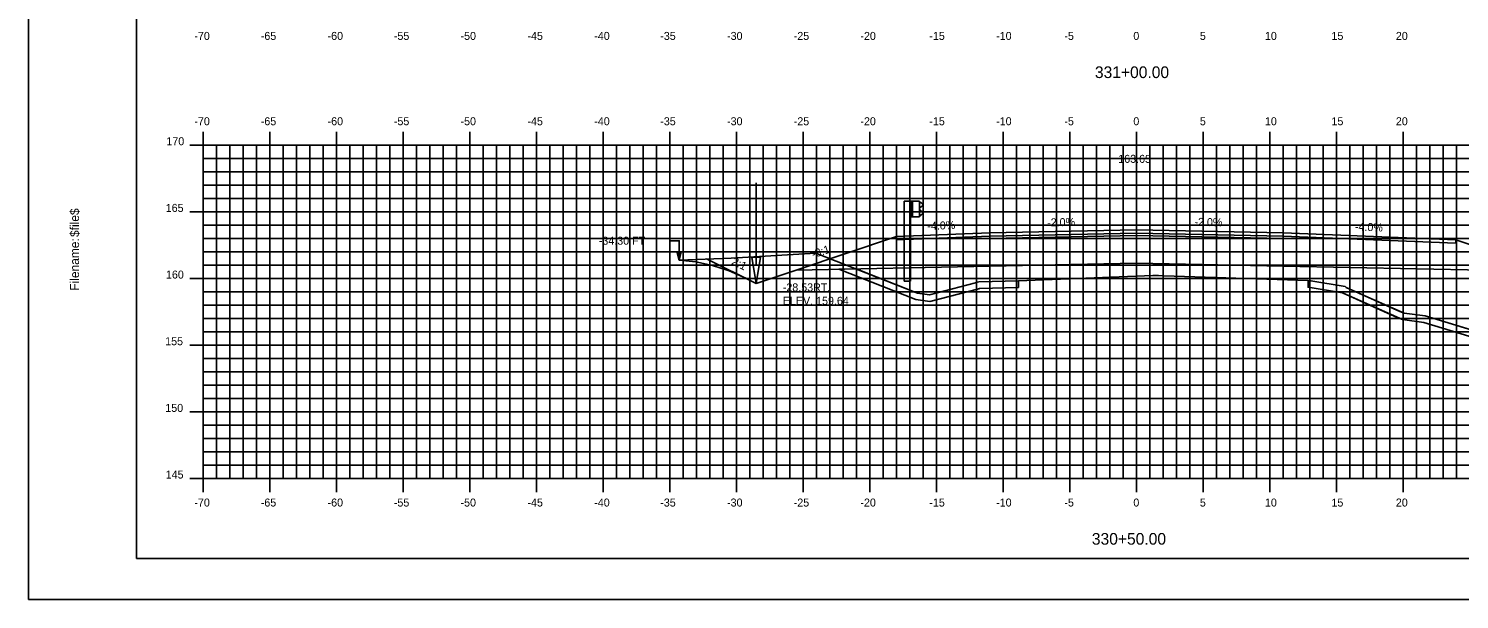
# Model space of a CAD drawing. Extents: x 1141424 to 1141594, y 608981 to 609091.
# Drawn here: x 1141424.2 to 1141531.5, y 608981.3 to 609024.1 of the extents above; entities that cross this region are included whole.
import ezdxf

# ---------------------------------------------------------------- set-up
doc = ezdxf.new("R2010")
doc.units = 0
for name, color, linetype in [('ANNOTATION', 7, 'Continuous'), ('BORDER', 7, 'Continuous'), ('D_Drainage_Ditch_Line', 7, 'Continuous'), ('D_Guardrail_Beam_Lt', 7, 'Continuous'), ('D_Roadway_Centerline', 7, 'Continuous'), ('D_Roadway_Centerline_Text', 7, 'Continuous'), ('D_Roadway_Edge_Shoulder', 7, 'Continuous'), ('D_Roadway_Edge_TW', 7, 'Continuous'), ('D_Roadway_Pavement', 7, 'Continuous'), ('D_Roadway_SlopeLines', 7, 'Continuous'), ('D_Roadway_SubGrade', 7, 'Continuous'), ('D_Text_Standard', 7, 'Continuous'), ('H_V ANNOTATION', 7, 'Continuous'), ('MAJOR', 7, 'Continuous'), ('MINOR', 7, 'Continuous'), ('PLOT BOUNDARY', 7, 'Continuous'), ('S_Roadway_Centerline', 7, 'Continuous'), ('SHADING', 7, 'Continuous')]:
    doc.layers.add(name, color=color, linetype=linetype)

msp = doc.modelspace()

# ---------------------------------------------------------------- linework, layer by layer
msp.add_lwpolyline([(1141475.03, 609006.83), (1141478.74, 609004.98), (1141481.74, 609005.98), (1141489.27, 609008.49), (1141489.27, 609008.49), (1141496.27, 609008.77), (1141507.27, 609008.99), (1141518.27, 609008.77), (1141531.21, 609008.25), (1141538.37, 609005.87), (1141541.37, 609004.87), (1141564.04, 608997.31)])
at = {"layer": 'BORDER'}
msp.add_lwpolyline([(1141432.27, 608984.34), (1141592.27, 608984.34), (1141592.27, 609089.34), (1141432.27, 609089.34)], close=True, dxfattribs=at)
at = {"layer": 'D_Drainage_Ditch_Line'}
msp.add_line((1141478.74, 609006.29), (1141478.74, 609012.53), dxfattribs=at)
msp.add_line((1141478.74, 609006.29), (1141478.74, 609012.53), dxfattribs=at)
msp.add_lwpolyline([(1141478.41, 609006.95), (1141479.07, 609006.95), (1141478.74, 609004.98)], close=True, dxfattribs=at)
msp.add_lwpolyline([(1141478.41, 609006.95), (1141479.07, 609006.95), (1141478.74, 609004.98)], close=True, dxfattribs=at)
at = {"layer": 'D_Guardrail_Beam_Lt'}
for p, q in [((1141489.84, 609011.15), (1141489.84, 609005.15)), ((1141490.31, 609011.15), (1141489.84, 609011.15)), ((1141491, 609011.15), (1141490.31, 609011.15)), ((1141490.31, 609011.15), (1141490.31, 609009.98)), ((1141490.37, 609011.15), (1141490.37, 609009.98)), ((1141490.48, 609011.15), (1141490.48, 609009.98)), ((1141491, 609009.98), (1141491, 609011.15)), ((1141491, 609011.07), (1141491.07, 609011.05)), ((1141491, 609010.6), (1141491, 609010.53)), ((1141491.23, 609010.8), (1141491.04, 609010.67)), ((1141491.04, 609010.47), (1141491.23, 609010.33)), ((1141491.09, 609011.05), (1141491.23, 609010.95)), ((1141490.31, 609009.98), (1141491, 609009.98)), ((1141490.33, 609005.15), (1141490.33, 609009.98)), ((1141491.07, 609010.08), (1141491, 609010.07)), ((1141491.23, 609010.19), (1141491.09, 609010.09)), ((1141490.33, 609005.15), (1141489.84, 609005.15))]:
    msp.add_line(p, q, dxfattribs=at)
for centre, major_axis, start_param, end_param in [((1141491.08, 609010.6), (-0.0789, 0), 5.323254, 6.283185), ((1141491.08, 609010.53), (-0.0789, 0), 6.283185, 7.243116), ((1141491.07, 609011.01), (0.0417, 0), 0.959931, 1.376053), ((1141491.18, 609010.88), (0.0877, 0), 5.323254, 7.243116), ((1141491.18, 609010.26), (0.0877, 0), 5.323254, 7.243116), ((1141491.07, 609010.12), (0.0417, 0), 4.907132, 5.323254)]:
    msp.add_ellipse(centre, major_axis=major_axis, ratio=0.995501, start_param=start_param, end_param=end_param, dxfattribs=at)
at = {"layer": 'D_Roadway_Edge_Shoulder'}
for points in [[(1141496.27, 609008.77), (1141489.27, 609008.49), (1141489.27, 609008.24), (1141496.27, 609008.52)], [(1141518.27, 609008.77), (1141531.21, 609008.25), (1141531.21, 609008), (1141518.27, 609008.52)]]:
    msp.add_lwpolyline(points, close=True, dxfattribs=at)
at = {"layer": 'D_Roadway_Edge_TW'}
msp.add_lwpolyline([(1141496.27, 609008.52), (1141496.27, 609008.77), (1141507.27, 609008.99), (1141518.27, 609008.77), (1141518.27, 609008.52), (1141507.27, 609008.74)], close=True, dxfattribs=at)
at = {"layer": 'D_Roadway_Pavement'}
msp.add_lwpolyline([(1141496.27, 609008.35), (1141496.27, 609008.52), (1141507.27, 609008.74), (1141518.27, 609008.52), (1141518.27, 609008.35), (1141507.27, 609008.57)], close=True, dxfattribs=at)
at = {"layer": 'D_Roadway_SlopeLines'}
for p, q in [((1141498.41, 609005.18), (1141498.41, 609004.68)), ((1141520.14, 609005.19), (1141520.14, 609004.69))]:
    msp.add_line(p, q, dxfattribs=at)
for points in [[(1141478.74, 609004.98), (1141477.97, 609005.36), (1141476.72, 609005.91), (1141475.47, 609006.33), (1141474.22, 609006.6), (1141472.97, 609006.72)], [(1141484.94, 609006.04), (1141490.71, 609003.76), (1141491.78, 609003.63), (1141495.35, 609004.54), (1141495.45, 609004.58), (1141495.5, 609004.59), (1141498.41, 609004.68)], [(1141481.74, 609005.98), (1141478.74, 609004.98)], [(1141520.14, 609004.69), (1141520.3, 609004.68), (1141522.72, 609004.26), (1141522.76, 609004.24), (1141526.82, 609002.42), (1141527.22, 609002.26), (1141528.81, 609002.05), (1141538.37, 608999.14)]]:
    msp.add_lwpolyline(points, dxfattribs=at)
at = {"layer": 'D_Roadway_SubGrade'}
for points in [[(1141496.27, 609008.35), (1141496.27, 609008.52), (1141489.27, 609008.24), (1141489.27, 609008.49), (1141489.27, 609008.49), (1141481.74, 609005.98), (1141496.27, 609006.27)], [(1141496.27, 609006.27), (1141496.27, 609008.35), (1141507.27, 609008.57), (1141518.27, 609008.35), (1141518.27, 609006.27), (1141507.27, 609006.49)], [(1141518.27, 609008.35), (1141518.27, 609008.52), (1141531.21, 609008), (1141531.21, 609008.25), (1141531.21, 609008.25), (1141538.37, 609005.87), (1141518.27, 609006.27)]]:
    msp.add_lwpolyline(points, close=True, dxfattribs=at)
at = {"layer": 'D_Text_Standard'}
msp.add_lwpolyline([(1141472.97, 609006.72), (1141472.97, 609008.18), (1141472.29, 609008.18)], dxfattribs=at)
msp.add_lwpolyline([(1141472.97, 609006.72), (1141472.83, 609007.3), (1141473.12, 609007.31)], close=True, dxfattribs=at)
at = {"layer": 'MAJOR'}
for p, q in [((1141437.27, 609016.34), (1141437.27, 609015.34)), ((1141442.27, 609016.34), (1141442.27, 609015.34)), ((1141447.27, 609016.34), (1141447.27, 609015.34)), ((1141452.27, 609016.34), (1141452.27, 609015.34)), ((1141457.27, 609016.34), (1141457.27, 609015.34)), ((1141462.27, 609016.34), (1141462.27, 609015.34)), ((1141467.27, 609016.34), (1141467.27, 609015.34)), ((1141472.27, 609016.34), (1141472.27, 609015.34)), ((1141477.27, 609016.34), (1141477.27, 609015.34)), ((1141482.27, 609016.34), (1141482.27, 609015.34)), ((1141487.27, 609016.34), (1141487.27, 609015.34)), ((1141492.27, 609016.34), (1141492.27, 609015.34)), ((1141497.27, 609016.34), (1141497.27, 609015.34)), ((1141502.27, 609016.34), (1141502.27, 609015.34)), ((1141507.27, 609016.34), (1141507.27, 609015.34)), ((1141512.27, 609016.34), (1141512.27, 609015.34)), ((1141517.27, 609016.34), (1141517.27, 609015.34)), ((1141522.27, 609016.34), (1141522.27, 609015.34)), ((1141527.27, 609016.34), (1141527.27, 609015.34)), ((1141436.27, 609015.34), (1141437.27, 609015.34)), ((1141437.27, 609015.34), (1141577.27, 609015.34)), ((1141437.27, 608990.34), (1141437.27, 609015.34)), ((1141437.27, 608990.34), (1141437.27, 609015.34)), ((1141437.27, 609015.34), (1141577.27, 609015.34)), ((1141442.27, 608990.34), (1141442.27, 609015.34)), ((1141447.27, 608990.34), (1141447.27, 609015.34)), ((1141452.27, 608990.34), (1141452.27, 609015.34)), ((1141457.27, 608990.34), (1141457.27, 609015.34)), ((1141462.27, 608990.34), (1141462.27, 609015.34)), ((1141467.27, 608990.34), (1141467.27, 609015.34)), ((1141472.27, 608990.34), (1141472.27, 609015.34)), ((1141477.27, 608990.34), (1141477.27, 609015.34)), ((1141482.27, 608990.34), (1141482.27, 609015.34)), ((1141487.27, 608990.34), (1141487.27, 609015.34)), ((1141492.27, 608990.34), (1141492.27, 609015.34)), ((1141497.27, 608990.34), (1141497.27, 609015.34)), ((1141502.27, 608990.34), (1141502.27, 609015.34)), ((1141507.27, 608990.34), (1141507.27, 609015.34)), ((1141512.27, 608990.34), (1141512.27, 609015.34)), ((1141517.27, 608990.34), (1141517.27, 609015.34)), ((1141522.27, 608990.34), (1141522.27, 609015.34)), ((1141527.27, 608990.34), (1141527.27, 609015.34)), ((1141436.27, 609010.34), (1141437.27, 609010.34)), ((1141437.27, 609010.34), (1141577.27, 609010.34)), ((1141436.27, 609005.34), (1141437.27, 609005.34)), ((1141437.27, 609005.34), (1141577.27, 609005.34)), ((1141436.27, 609000.34), (1141437.27, 609000.34)), ((1141437.27, 609000.34), (1141577.27, 609000.34)), ((1141436.27, 608995.34), (1141437.27, 608995.34)), ((1141437.27, 608995.34), (1141577.27, 608995.34)), ((1141436.27, 608990.34), (1141437.27, 608990.34)), ((1141437.27, 608990.34), (1141577.27, 608990.34)), ((1141437.27, 608990.34), (1141577.27, 608990.34)), ((1141437.27, 608989.33), (1141437.27, 608990.34)), ((1141442.27, 608989.33), (1141442.27, 608990.34)), ((1141447.27, 608989.33), (1141447.27, 608990.34)), ((1141452.27, 608989.33), (1141452.27, 608990.34)), ((1141457.27, 608989.33), (1141457.27, 608990.34)), ((1141462.27, 608989.33), (1141462.27, 608990.34)), ((1141467.27, 608989.33), (1141467.27, 608990.34)), ((1141472.27, 608989.33), (1141472.27, 608990.34)), ((1141477.27, 608989.33), (1141477.27, 608990.34)), ((1141482.27, 608989.33), (1141482.27, 608990.34)), ((1141487.27, 608989.33), (1141487.27, 608990.34)), ((1141492.27, 608989.33), (1141492.27, 608990.34)), ((1141497.27, 608989.33), (1141497.27, 608990.34)), ((1141502.27, 608989.33), (1141502.27, 608990.34)), ((1141507.27, 608989.33), (1141507.27, 608990.34)), ((1141512.27, 608989.33), (1141512.27, 608990.34)), ((1141517.27, 608989.33), (1141517.27, 608990.34)), ((1141522.27, 608989.33), (1141522.27, 608990.34)), ((1141527.27, 608989.33), (1141527.27, 608990.34))]:
    msp.add_line(p, q, dxfattribs=at)
at = {"layer": 'MINOR'}
for p, q in [((1141438.27, 608990.34), (1141438.27, 609015.34)), ((1141439.27, 608990.34), (1141439.27, 609015.34)), ((1141440.27, 608990.34), (1141440.27, 609015.34)), ((1141441.27, 608990.34), (1141441.27, 609015.34)), ((1141443.27, 608990.34), (1141443.27, 609015.34)), ((1141444.27, 608990.34), (1141444.27, 609015.34)), ((1141445.27, 608990.34), (1141445.27, 609015.34)), ((1141446.27, 608990.34), (1141446.27, 609015.34)), ((1141448.27, 608990.34), (1141448.27, 609015.34)), ((1141449.27, 608990.34), (1141449.27, 609015.34)), ((1141450.27, 608990.34), (1141450.27, 609015.34)), ((1141451.27, 608990.34), (1141451.27, 609015.34)), ((1141453.27, 608990.34), (1141453.27, 609015.34)), ((1141454.27, 608990.34), (1141454.27, 609015.34)), ((1141455.27, 608990.34), (1141455.27, 609015.34)), ((1141456.27, 608990.34), (1141456.27, 609015.34)), ((1141458.27, 608990.34), (1141458.27, 609015.34)), ((1141459.27, 608990.34), (1141459.27, 609015.34)), ((1141460.27, 608990.34), (1141460.27, 609015.34)), ((1141461.27, 608990.34), (1141461.27, 609015.34)), ((1141463.27, 608990.34), (1141463.27, 609015.34)), ((1141464.27, 608990.34), (1141464.27, 609015.34)), ((1141465.27, 608990.34), (1141465.27, 609015.34)), ((1141466.27, 608990.34), (1141466.27, 609015.34)), ((1141468.27, 608990.34), (1141468.27, 609015.34)), ((1141469.27, 608990.34), (1141469.27, 609015.34)), ((1141470.27, 608990.34), (1141470.27, 609015.34)), ((1141471.27, 608990.34), (1141471.27, 609015.34)), ((1141473.27, 608990.34), (1141473.27, 609015.34)), ((1141474.27, 608990.34), (1141474.27, 609015.34)), ((1141475.27, 608990.34), (1141475.27, 609015.34)), ((1141476.27, 608990.34), (1141476.27, 609015.34)), ((1141478.27, 608990.34), (1141478.27, 609015.34)), ((1141479.27, 608990.34), (1141479.27, 609015.34)), ((1141480.27, 608990.34), (1141480.27, 609015.34)), ((1141481.27, 608990.34), (1141481.27, 609015.34)), ((1141483.27, 608990.34), (1141483.27, 609015.34)), ((1141484.27, 608990.34), (1141484.27, 609015.34)), ((1141485.27, 608990.34), (1141485.27, 609015.34)), ((1141486.27, 608990.34), (1141486.27, 609015.34)), ((1141488.27, 608990.34), (1141488.27, 609015.34)), ((1141489.27, 608990.34), (1141489.27, 609015.34)), ((1141490.27, 608990.34), (1141490.27, 609015.34)), ((1141491.27, 608990.34), (1141491.27, 609015.34)), ((1141493.27, 608990.34), (1141493.27, 609015.34)), ((1141494.27, 608990.34), (1141494.27, 609015.34)), ((1141495.27, 608990.34), (1141495.27, 609015.34)), ((1141496.27, 608990.34), (1141496.27, 609015.34)), ((1141498.27, 608990.34), (1141498.27, 609015.34)), ((1141499.27, 608990.34), (1141499.27, 609015.34)), ((1141500.27, 608990.34), (1141500.27, 609015.34)), ((1141501.27, 608990.34), (1141501.27, 609015.34)), ((1141503.27, 608990.34), (1141503.27, 609015.34)), ((1141504.27, 608990.34), (1141504.27, 609015.34)), ((1141505.27, 608990.34), (1141505.27, 609015.34)), ((1141506.27, 608990.34), (1141506.27, 609015.34)), ((1141508.27, 608990.34), (1141508.27, 609015.34)), ((1141509.27, 608990.34), (1141509.27, 609015.34)), ((1141510.27, 608990.34), (1141510.27, 609015.34)), ((1141511.27, 608990.34), (1141511.27, 609015.34)), ((1141513.27, 608990.34), (1141513.27, 609015.34)), ((1141514.27, 608990.34), (1141514.27, 609015.34)), ((1141515.27, 608990.34), (1141515.27, 609015.34)), ((1141516.27, 608990.34), (1141516.27, 609015.34)), ((1141518.27, 608990.34), (1141518.27, 609015.34)), ((1141519.27, 608990.34), (1141519.27, 609015.34)), ((1141520.27, 608990.34), (1141520.27, 609015.34)), ((1141521.27, 608990.34), (1141521.27, 609015.34)), ((1141523.27, 608990.34), (1141523.27, 609015.34)), ((1141524.27, 608990.34), (1141524.27, 609015.34)), ((1141525.27, 608990.34), (1141525.27, 609015.34)), ((1141526.27, 608990.34), (1141526.27, 609015.34)), ((1141528.27, 608990.34), (1141528.27, 609015.34)), ((1141529.27, 608990.34), (1141529.27, 609015.34)), ((1141530.27, 608990.34), (1141530.27, 609015.34)), ((1141531.27, 608990.34), (1141531.27, 609015.34)), ((1141437.27, 609014.34), (1141577.27, 609014.34)), ((1141437.27, 609014.34), (1141438.27, 609014.34)), ((1141437.27, 609013.34), (1141577.27, 609013.34)), ((1141437.27, 609013.34), (1141438.27, 609013.34)), ((1141437.27, 609012.34), (1141577.27, 609012.34)), ((1141437.27, 609012.34), (1141438.27, 609012.34)), ((1141437.27, 609011.34), (1141577.27, 609011.34)), ((1141437.27, 609011.34), (1141438.27, 609011.34)), ((1141437.27, 609009.34), (1141577.27, 609009.34)), ((1141437.27, 609009.34), (1141438.27, 609009.34)), ((1141437.27, 609008.34), (1141577.27, 609008.34)), ((1141437.27, 609008.34), (1141438.27, 609008.34)), ((1141437.27, 609007.34), (1141577.27, 609007.34)), ((1141437.27, 609007.34), (1141438.27, 609007.34)), ((1141437.27, 609006.34), (1141577.27, 609006.34)), ((1141437.27, 609006.34), (1141438.27, 609006.34)), ((1141437.27, 609004.34), (1141577.27, 609004.34)), ((1141437.27, 609004.34), (1141438.27, 609004.34)), ((1141437.27, 609003.34), (1141577.27, 609003.34)), ((1141437.27, 609003.34), (1141438.27, 609003.34)), ((1141437.27, 609002.34), (1141577.27, 609002.34)), ((1141437.27, 609002.34), (1141438.27, 609002.34)), ((1141437.27, 609001.34), (1141577.27, 609001.34)), ((1141437.27, 609001.34), (1141438.27, 609001.34)), ((1141437.27, 608999.34), (1141577.27, 608999.34)), ((1141437.27, 608999.34), (1141438.27, 608999.34)), ((1141437.27, 608998.34), (1141577.27, 608998.34)), ((1141437.27, 608998.34), (1141438.27, 608998.34)), ((1141437.27, 608997.34), (1141577.27, 608997.34)), ((1141437.27, 608997.34), (1141438.27, 608997.34)), ((1141437.27, 608996.34), (1141577.27, 608996.34)), ((1141437.27, 608996.34), (1141438.27, 608996.34)), ((1141437.27, 608994.34), (1141577.27, 608994.34)), ((1141437.27, 608994.34), (1141438.27, 608994.34)), ((1141437.27, 608993.34), (1141577.27, 608993.34)), ((1141437.27, 608993.34), (1141438.27, 608993.34)), ((1141437.27, 608992.34), (1141577.27, 608992.34)), ((1141437.27, 608992.34), (1141438.27, 608992.34)), ((1141437.27, 608991.34), (1141577.27, 608991.34)), ((1141437.27, 608991.34), (1141438.27, 608991.34))]:
    msp.add_line(p, q, dxfattribs=at)
at = {"layer": 'PLOT BOUNDARY'}
msp.add_lwpolyline([(1141424.18, 608981.28), (1141594.18, 608981.28), (1141594.18, 609091.28), (1141424.18, 609091.28)], close=True, dxfattribs=at)
at = {"layer": 'S_Roadway_Centerline'}
msp.add_lwpolyline([(1141472.97, 609006.72), (1141476.86, 609006.87), (1141483.23, 609007.25), (1141490.84, 609004.25), (1141491.75, 609004.13), (1141495.19, 609005.02), (1141495.31, 609005.07), (1141495.45, 609005.09), (1141498.41, 609005.18), (1141508.49, 609005.56), (1141508.91, 609005.57), (1141509.32, 609005.55), (1141520.14, 609005.19), (1141520.35, 609005.18), (1141522.91, 609004.74), (1141523, 609004.68), (1141527.02, 609002.88), (1141527.35, 609002.75), (1141528.92, 609002.54), (1141539.49, 608999.32)], dxfattribs=at)
at = {"layer": 'SHADING'}
for p, q in [((1141486.24, 609006.07), (1141484.94, 609006.04)), ((1141498.41, 609004.68), (1141498.41, 609005.18))]:
    msp.add_line(p, q, dxfattribs=at)
for points in [[(1141484.94, 609006.04), (1141490.71, 609003.76), (1141491.78, 609003.63), (1141495.35, 609004.54), (1141495.5, 609004.59), (1141498.41, 609004.68)], [(1141498.41, 609005.18), (1141495.45, 609005.09), (1141495.31, 609005.07), (1141495.19, 609005.02), (1141491.75, 609004.13), (1141490.84, 609004.25), (1141486.24, 609006.07)]]:
    msp.add_lwpolyline(points, dxfattribs=at)
msp.add_lwpolyline([(1141520.14, 609005.19), (1141520.14, 609004.69), (1141522.72, 609004.26), (1141527.22, 609002.26), (1141528.81, 609002.05), (1141538.37, 608999.14), (1141538.37, 608999.66), (1141528.92, 609002.54), (1141527.35, 609002.75), (1141525.01, 609003.78), (1141523, 609004.68), (1141522.91, 609004.74), (1141520.35, 609005.18)], close=True, dxfattribs=at)

# ---------------------------------------------------------------- texts
at = {"layer": 'ANNOTATION'}
for s, rotation, p in [('-4.0%', 2.2906, (1141491.59, 609008.98)), ('-2.0%', 1.1458, (1141500.57, 609009.25)), ('-2.0%', 358.8542, (1141511.61, 609009.3)), ('-4.0%', 357.7094, (1141523.64, 609008.95)), ('-3:1', 18.4348, (1141483.02, 609006.86)), ('2:1', 333.4349, (1141476.85, 609006.44))]:
    msp.add_text(s, height=0.6, rotation=rotation, dxfattribs=at).set_placement(p)
at = {"layer": 'BORDER'}
for s, p in [('$file$', (1141427.96, 609008.46)), ('Filename:', (1141427.96, 609004.43))]:
    msp.add_text(s, height=0.67, rotation=90, dxfattribs=at).set_placement(p)
at = {"layer": 'D_Roadway_Centerline'}
for s, p in [('C', (1141507.27, 609008.99)), ('C', (1141507.27, 609008.99)), ('L', (1141507.27, 609008.98)), ('L', (1141507.27, 609008.98))]:
    msp.add_text(s, height=0.0146, dxfattribs=at).set_placement(p)
at = {"layer": 'D_Roadway_Centerline_Text'}
msp.add_text('163.65', height=0.6, dxfattribs=at).set_placement((1141505.9, 609014.02))
at = {"layer": 'D_Text_Standard'}
for s, p in [('-34.30 FT', (1141466.94, 609007.88)), ('-28.53', (1141480.74, 609004.38)), ('-28.53RT.', (1141480.74, 609004.38)), ('ELEV. 159.64', (1141480.74, 609003.37)), ('ELEV. 159.64', (1141480.74, 609003.37))]:
    msp.add_text(s, height=0.6, dxfattribs=at).set_placement(p)
at = {"layer": 'H_V ANNOTATION'}
for s, height, p in [('-70', 0.6, (1141436.61, 609023.24)), ('-65', 0.6, (1141441.59, 609023.24)), ('-60', 0.6, (1141446.6, 609023.24)), ('-55', 0.6, (1141451.57, 609023.24)), ('-50', 0.6, (1141456.57, 609023.24)), ('-45', 0.6, (1141461.59, 609023.24)), ('-40', 0.6, (1141466.6, 609023.24)), ('-35', 0.6, (1141471.55, 609023.24)), ('-30', 0.6, (1141476.56, 609023.24)), ('-25', 0.6, (1141481.56, 609023.24)), ('-20', 0.6, (1141486.56, 609023.24)), ('-15', 0.6, (1141491.73, 609023.24)), ('-10', 0.6, (1141496.74, 609023.24)), ('-5', 0.6, (1141501.86, 609023.24)), ('0', 0.6, (1141507.03, 609023.24)), ('5', 0.6, (1141512.02, 609023.24)), ('10', 0.6, (1141516.9, 609023.24)), ('15', 0.6, (1141521.89, 609023.24)), ('20', 0.6, (1141526.72, 609023.24)), ('331+00.00', 0.875, (1141504.15, 609020.38)), ('-70', 0.6, (1141436.61, 609016.84)), ('-65', 0.6, (1141441.59, 609016.84)), ('-60', 0.6, (1141446.6, 609016.84)), ('-55', 0.6, (1141451.57, 609016.84)), ('-50', 0.6, (1141456.57, 609016.84)), ('-45', 0.6, (1141461.59, 609016.84)), ('-40', 0.6, (1141466.6, 609016.84)), ('-35', 0.6, (1141471.55, 609016.84)), ('-30', 0.6, (1141476.56, 609016.84)), ('-25', 0.6, (1141481.56, 609016.84)), ('-20', 0.6, (1141486.56, 609016.84)), ('-15', 0.6, (1141491.73, 609016.84)), ('-10', 0.6, (1141496.74, 609016.84)), ('-5', 0.6, (1141501.86, 609016.84)), ('0', 0.6, (1141507.03, 609016.84)), ('5', 0.6, (1141512.02, 609016.84)), ('10', 0.6, (1141516.9, 609016.84)), ('15', 0.6, (1141521.89, 609016.84)), ('20', 0.6, (1141526.72, 609016.84)), ('170', 0.6, (1141434.51, 609015.34)), ('165', 0.6, (1141434.46, 609010.34)), ('160', 0.6, (1141434.48, 609005.34)), ('155', 0.6, (1141434.42, 609000.34)), ('150', 0.6, (1141434.43, 608995.34)), ('145', 0.6, (1141434.46, 608990.34)), ('-70', 0.6, (1141436.61, 608988.24)), ('-65', 0.6, (1141441.59, 608988.24)), ('-60', 0.6, (1141446.6, 608988.24)), ('-50', 0.6, (1141456.57, 608988.24)), ('-40', 0.6, (1141466.6, 608988.24)), ('-35', 0.6, (1141471.55, 608988.24)), ('-30', 0.6, (1141476.56, 608988.24)), ('-25', 0.6, (1141481.56, 608988.24)), ('-20', 0.6, (1141486.56, 608988.24)), ('-10', 0.6, (1141496.74, 608988.24)), ('0', 0.6, (1141507.03, 608988.24)), ('10', 0.6, (1141516.9, 608988.24)), ('20', 0.6, (1141526.72, 608988.24)), ('-55', 0.6, (1141451.57, 608988.24)), ('-45', 0.6, (1141461.59, 608988.24)), ('-15', 0.6, (1141491.73, 608988.24)), ('-5', 0.6, (1141501.86, 608988.24)), ('5', 0.6, (1141512.02, 608988.24)), ('15', 0.6, (1141521.89, 608988.24)), ('330+50.00', 0.875, (1141503.92, 608985.38))]:
    msp.add_text(s, height=height, dxfattribs=at).set_placement(p)
at = {"layer": 'MAJOR'}
msp.add_text('-', height=0.006, dxfattribs=at).set_placement((1141437.27, 608990.34))
at = {"layer": 'S_Roadway_Centerline'}
for s, p in [('C', (1141508.9, 609005.57)), ('L', (1141508.91, 609005.56))]:
    msp.add_text(s, height=0.0146, dxfattribs=at).set_placement(p)

doc.saveas('drawing.dxf')
